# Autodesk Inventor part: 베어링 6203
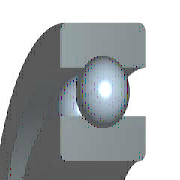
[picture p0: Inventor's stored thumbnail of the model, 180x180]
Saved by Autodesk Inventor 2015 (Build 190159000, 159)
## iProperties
IsCustomPart: 1
Created: 2012-02
Part Number: 베어링 6203
Material: 강철, 연강
Description: 깊은 그루브 볼 베어링
Document SubType Name: Modeling
Standard: KS B 2023
Designer: mduedu
Standards Organization: KS
Language: ko-KR
Size Designation: 6203 - 17 x 40 x 12
Categories: <MemberInstance><Categories><Category DisplayName="샤프트 부품" InternalName="7f7aeb1f-a693-4053-b835-cee3144e0d98" Mnemonic="SHFT"><Category DisplayName="베어링" Inter
Density: 1 g/cm^3
Appearance: 노란색
Author: mduedu
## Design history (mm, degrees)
sketch "스케치" dims "d0" = 5.98 (= -0.26 x WD + 0.26 x BD)
  geometry: L1 (3.01, 14.25)-(8.99, 14.25); L2 (6, 14.25)-(6, 11.26); L3 (6, 14.25)-(6, 17.24); L4 (3.778, 12.249)-(0, 12.249); L5 (0, 8.5)-(12, 8.5); L6 (3.778, 16.251)-(0, 16.251); L7 (0, 20)-(12, 20); L8 (12, 8.5)-(12, 12.249); L9 (8.222, 12.249)-(12, 12.249); L10 (8.222, 16.251)-(12, 16.251); L11 (12, 20)-(12, 16.251); L12 (-1.4, 0)-(8.4, 0) reference; L13 (0, -0.3)-(0, 5.3) reference
  constraints: 22 end point, 4 point on line, 2 collinear, 2 perpendicular, 2 symmetric about line, 1 midpoint, 1 parallel, 14 other
  dimensions: "d9" = 17 diameter of L5 L12 (= WD); "d11" = 40 diameter of L7 L12 (= BD); "d12" = 12 distance between parallel lines of L8 L13 (= KB); "d13" = 24.498 diameter of L9 L12 (= 0.326 x BD + 0.674 x WD)
revolve "본체" stored, may be unused: angle "d6" = 90 deg
revolve "볼" stored, may be unused: angle "d7" = 90 deg
pattern_circular "IDS_ARRAYBALL[SIMPL:T]" dims angle "d3" = 360 deg
body "Solid1"
fillet "모깎기1" dims "d1" = 0.6 (= KRS)
other parameters: "WD" = 17 [user parameter; used in 5 equation terms], "BD" = 40 [user parameter; used in 5 equation terms], "KB" = 12 [user parameter; used in 1 equation term], "KRS" = 0.6 [user parameter; used in 1 equation term], "d4" = 0, "d5" = 0, "d8" = 0, "d14" = 0, "d15" = 0, "BBA" = 0 [user parameter], "BC0" = 4750000 [user parameter], "BC" = 9560000 [user parameter], "WR" = 8.5 (= 0.5 x WD) [user parameter]
